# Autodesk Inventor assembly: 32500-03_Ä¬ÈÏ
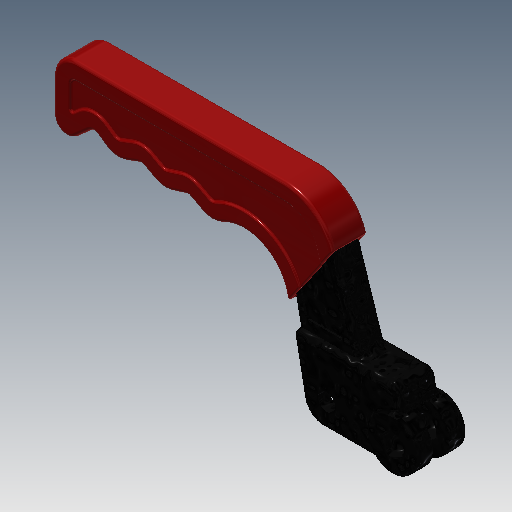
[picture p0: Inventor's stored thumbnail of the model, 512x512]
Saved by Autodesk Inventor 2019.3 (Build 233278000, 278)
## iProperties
Created: 2010-06
Part Number: 32500-03_Ä¬ÈÏ
Material: Ogólny
Document SubType Name: Assembly
Designer: CADENGINEERING4
Author: CADENGINEERING4
Revision Number: ÈÎºÎ
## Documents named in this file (3)
- D:\Vault_2016\Projekty\STRONA\Push-pull clamp\CH-32500\32500-03_Ä¬ÈÏ.iam
- D:\Vault_2016\Projekty\STRONA\Push-pull clamp\CH-32500\32500-03_Ä¬ÈÏ.ipt
- D:\Vault_2016\Projekty\STRONA\Push-pull clamp\CH-32500\32500-03-1_Ä¬ÈÏ.ipt
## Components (2 placed, 2 different names)
1. 32500-03_Ä¬ÈÏ_11
2. 32500-03-1_Ä¬ÈÏ_12
